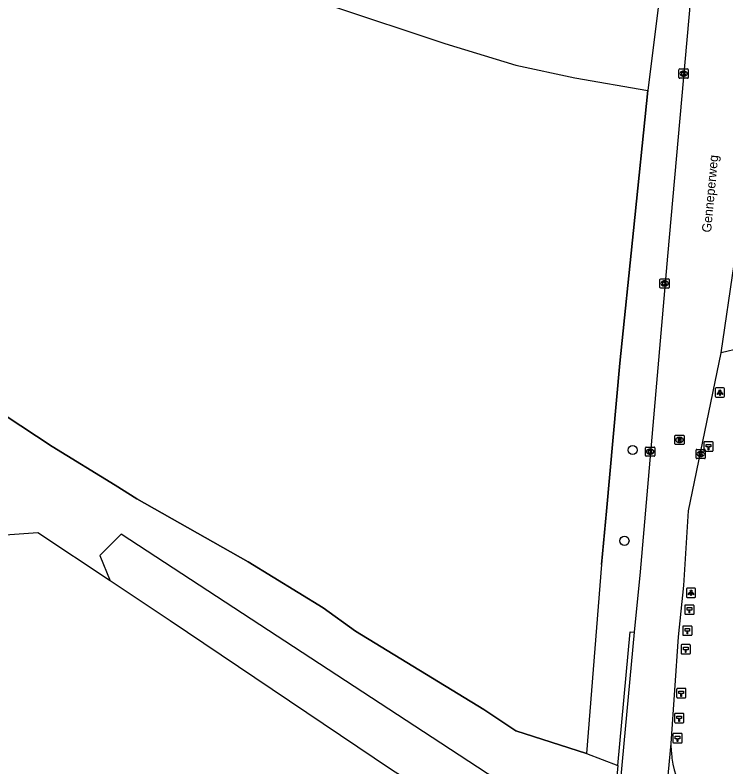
# Model space of a CAD drawing. Extents: x 160203 to 161526, y 379529 to 381797.
# Drawn here: x 160739.6 to 160816.3, y 380561.5 to 380642.7 of the extents above; entities that cross this region are included whole.
import ezdxf

# ---------------------------------------------------------------- set-up
doc = ezdxf.new("R2010")
doc.units = 0
for name, color, linetype in [('IMGEO_Boom', 7, 'Continuous'), ('IMGEO_Grasland_agrarisch', 7, 'Continuous'), ('IMGEO_Groenvoorziening', 7, 'Continuous'), ('IMGEO_Hectometerpaal', 7, 'Continuous'), ('IMGEO_Hek', 7, 'Continuous'), ('IMGEO_Kolk', 7, 'Continuous'), ('IMGEO_Lichtpunt', 7, 'Continuous'), ('IMGEO_Loofbos', 7, 'Continuous'), ('IMGEO_Openbare_ruimte_label', 7, 'Continuous'), ('IMGEO_Rijbaan_lokaal_gesloten', 7, 'Continuous'), ('IMGEO_Rijbaan_lokaal_open', 7, 'Continuous'), ('IMGEO_Rioolput', 7, 'Continuous'), ('IMGEO_Voetpad_onverhard', 7, 'Continuous')]:
    doc.layers.add(name, color=color, linetype=linetype)

msp = doc.modelspace()

# ---------------------------------------------------------------- linework, layer by layer
at = {"layer": 'IMGEO_Boom'}
for centre in [(160806.245, 380595.691), (160805.36, 380585.891)]:
    msp.add_circle(centre, 0.489, dxfattribs=at)
at = {"layer": 'IMGEO_Grasland_agrarisch'}
for points in [[(160735.875, 380657.838), (160759.659, 380648.601), (160773.611, 380643.676), (160785.98, 380639.572), (160793.624, 380637.245), (160800.015, 380635.877), (160807.89, 380634.509)], [(160807.89, 380634.509), (160806.333, 380619.409), (160804.861, 380605.066), (160803.41, 380589.083), (160802.874, 380583.321), (160801.244, 380562.921)]]:
    msp.add_lwpolyline(points, dxfattribs=at)
at = {"layer": 'IMGEO_Groenvoorziening'}
msp.add_lwpolyline([(160811.37, 380663.358), (160811.078, 380660.23), (160807.89, 380634.509)], dxfattribs=at)
at = {"layer": 'IMGEO_Hectometerpaal'}
for p, q in [((160813.932, 380596.495), (160813.932, 380595.654)), ((160813.932, 380596.495), (160813.932, 380595.654)), ((160814.848, 380596.579), (160814.007, 380596.579)), ((160814.848, 380596.579), (160814.007, 380596.579)), ((160814.932, 380595.663), (160814.932, 380596.504)), ((160814.932, 380595.663), (160814.932, 380596.504)), ((160814.016, 380595.579), (160814.857, 380595.579)), ((160814.016, 380595.579), (160814.857, 380595.579)), ((160811.87, 380578.876), (160811.87, 380578.035)), ((160811.87, 380578.876), (160811.87, 380578.035)), ((160812.786, 380578.96), (160811.945, 380578.96)), ((160812.786, 380578.96), (160811.945, 380578.96)), ((160812.87, 380578.044), (160812.87, 380578.885)), ((160812.87, 380578.044), (160812.87, 380578.885)), ((160811.954, 380577.96), (160812.795, 380577.96)), ((160811.954, 380577.96), (160812.795, 380577.96)), ((160811.65, 380576.61), (160811.65, 380575.769)), ((160811.65, 380576.61), (160811.65, 380575.769)), ((160812.566, 380576.694), (160811.725, 380576.694)), ((160812.566, 380576.694), (160811.725, 380576.694)), ((160812.65, 380575.778), (160812.65, 380576.619)), ((160812.65, 380575.778), (160812.65, 380576.619)), ((160811.734, 380575.694), (160812.575, 380575.694)), ((160811.734, 380575.694), (160812.575, 380575.694)), ((160811.475, 380574.602), (160811.475, 380573.761)), ((160811.475, 380574.602), (160811.475, 380573.761)), ((160812.391, 380574.686), (160811.55, 380574.686)), ((160812.391, 380574.686), (160811.55, 380574.686)), ((160812.475, 380573.77), (160812.475, 380574.611)), ((160812.475, 380573.77), (160812.475, 380574.611)), ((160811.559, 380573.686), (160812.4, 380573.686)), ((160811.559, 380573.686), (160812.4, 380573.686)), ((160811.909, 380569.951), (160811.068, 380569.951)), ((160811.909, 380569.951), (160811.068, 380569.951)), ((160810.993, 380569.867), (160810.993, 380569.026)), ((160810.993, 380569.867), (160810.993, 380569.026)), ((160811.993, 380569.035), (160811.993, 380569.876)), ((160811.993, 380569.035), (160811.993, 380569.876)), ((160811.077, 380568.951), (160811.918, 380568.951)), ((160811.077, 380568.951), (160811.918, 380568.951)), ((160810.763, 380567.172), (160810.763, 380566.331)), ((160810.763, 380567.172), (160810.763, 380566.331)), ((160811.679, 380567.256), (160810.838, 380567.256)), ((160811.679, 380567.256), (160810.838, 380567.256)), ((160811.763, 380566.34), (160811.763, 380567.181)), ((160811.763, 380566.34), (160811.763, 380567.181)), ((160810.847, 380566.256), (160811.688, 380566.256)), ((160810.847, 380566.256), (160811.688, 380566.256)), ((160811.503, 380565.081), (160810.662, 380565.081)), ((160811.503, 380565.081), (160810.662, 380565.081)), ((160810.587, 380564.997), (160810.587, 380564.156)), ((160810.587, 380564.997), (160810.587, 380564.156)), ((160811.587, 380564.165), (160811.587, 380565.006)), ((160811.587, 380564.165), (160811.587, 380565.006)), ((160810.671, 380564.081), (160811.512, 380564.081)), ((160810.671, 380564.081), (160811.512, 380564.081))]:
    msp.add_line(p, q, dxfattribs=at)
for points in [[(160814.457, 380595.723), (160814.397, 380595.723), (160814.397, 380596.028), (160814.177, 380596.028), (160814.177, 380596.297), (160814.677, 380596.297), (160814.677, 380596.028), (160814.457, 380596.028), (160814.457, 380595.723)], [(160812.395, 380578.104), (160812.335, 380578.104), (160812.335, 380578.409), (160812.115, 380578.409), (160812.115, 380578.678), (160812.615, 380578.678), (160812.615, 380578.409), (160812.395, 380578.409), (160812.395, 380578.104)], [(160812.175, 380575.838), (160812.115, 380575.838), (160812.115, 380576.143), (160811.895, 380576.143), (160811.895, 380576.412), (160812.395, 380576.412), (160812.395, 380576.143), (160812.175, 380576.143), (160812.175, 380575.838)], [(160812, 380573.83), (160811.94, 380573.83), (160811.94, 380574.135), (160811.72, 380574.135), (160811.72, 380574.404), (160812.22, 380574.404), (160812.22, 380574.135), (160812, 380574.135), (160812, 380573.83)], [(160811.518, 380569.095), (160811.458, 380569.095), (160811.458, 380569.4), (160811.238, 380569.4), (160811.238, 380569.669), (160811.738, 380569.669), (160811.738, 380569.4), (160811.518, 380569.4), (160811.518, 380569.095)], [(160811.288, 380566.4), (160811.228, 380566.4), (160811.228, 380566.705), (160811.008, 380566.705), (160811.008, 380566.974), (160811.508, 380566.974), (160811.508, 380566.705), (160811.288, 380566.705), (160811.288, 380566.4)], [(160811.112, 380564.225), (160811.052, 380564.225), (160811.052, 380564.53), (160810.832, 380564.53), (160810.832, 380564.799), (160811.332, 380564.799), (160811.332, 380564.53), (160811.112, 380564.53), (160811.112, 380564.225)]]:
    msp.add_lwpolyline(points, dxfattribs=at)
for centre, start, end in [((160814.01, 380596.501), 92.4484, 184.28452), ((160814.01, 380596.501), 92.4484, 184.28452), ((160814.854, 380596.501), 2.4484, 94.28452), ((160814.854, 380596.501), 2.4484, 94.28452), ((160814.01, 380595.657), 182.4484, 274.28452), ((160814.01, 380595.657), 182.4484, 274.28452), ((160814.854, 380595.657), 272.4484, 4.28452), ((160814.854, 380595.657), 272.4484, 4.28452), ((160811.948, 380578.882), 92.4484, 184.28452), ((160811.948, 380578.882), 92.4484, 184.28452), ((160812.792, 380578.882), 2.4484, 94.28452), ((160812.792, 380578.882), 2.4484, 94.28452), ((160811.948, 380578.038), 182.4484, 274.28452), ((160811.948, 380578.038), 182.4484, 274.28452), ((160812.792, 380578.038), 272.4484, 4.28452), ((160812.792, 380578.038), 272.4484, 4.28452), ((160811.728, 380576.616), 92.4484, 184.28452), ((160811.728, 380576.616), 92.4484, 184.28452), ((160812.572, 380576.616), 2.4484, 94.28452), ((160812.572, 380576.616), 2.4484, 94.28452), ((160811.728, 380575.772), 182.4484, 274.28452), ((160811.728, 380575.772), 182.4484, 274.28452), ((160812.572, 380575.772), 272.4484, 4.28452), ((160812.572, 380575.772), 272.4484, 4.28452), ((160811.553, 380574.608), 92.4484, 184.28452), ((160811.553, 380574.608), 92.4484, 184.28452), ((160812.397, 380574.608), 2.4484, 94.28452), ((160812.397, 380574.608), 2.4484, 94.28452), ((160811.553, 380573.764), 182.4484, 274.28452), ((160811.553, 380573.764), 182.4484, 274.28452), ((160812.397, 380573.764), 272.4484, 4.28452), ((160812.397, 380573.764), 272.4484, 4.28452), ((160811.071, 380569.873), 92.4484, 184.28452), ((160811.071, 380569.873), 92.4484, 184.28452), ((160811.915, 380569.873), 2.4484, 94.28452), ((160811.915, 380569.873), 2.4484, 94.28452), ((160811.071, 380569.029), 182.4484, 274.28452), ((160811.071, 380569.029), 182.4484, 274.28452), ((160811.915, 380569.029), 272.4484, 4.28452), ((160811.915, 380569.029), 272.4484, 4.28452), ((160810.841, 380567.178), 92.4484, 184.28452), ((160810.841, 380567.178), 92.4484, 184.28452), ((160811.685, 380567.178), 2.4484, 94.28452), ((160811.685, 380567.178), 2.4484, 94.28452), ((160810.841, 380566.334), 182.4484, 274.28452), ((160810.841, 380566.334), 182.4484, 274.28452), ((160811.685, 380566.334), 272.4484, 4.28452), ((160811.685, 380566.334), 272.4484, 4.28452), ((160810.665, 380565.003), 92.4484, 184.28452), ((160810.665, 380565.003), 92.4484, 184.28452), ((160811.509, 380565.003), 2.4484, 94.28452), ((160811.509, 380565.003), 2.4484, 94.28452), ((160810.665, 380564.159), 182.4484, 274.28452), ((160810.665, 380564.159), 182.4484, 274.28452), ((160811.509, 380564.159), 272.4484, 4.28452), ((160811.509, 380564.159), 272.4484, 4.28452)]:
    msp.add_arc(centre, 0.0779, start, end, dxfattribs=at)
at = {"layer": 'IMGEO_Hek'}
for points in [[(160802.874, 380583.321), (160803.41, 380589.083), (160804.861, 380605.066), (160806.333, 380619.409), (160807.89, 380634.509)], [(160721.585, 380611.503), (160724.413, 380609.361), (160726.913, 380607.468), (160734.981, 380601.724), (160743.595, 380596.079), (160750.384, 380591.884), (160752.717, 380590.443), (160764.753, 380583.637), (160772.849, 380578.66), (160776.314, 380576.149), (160790.192, 380567.674), (160793.641, 380565.361), (160801.244, 380562.921)]]:
    msp.add_lwpolyline(points, dxfattribs=at)
at = {"layer": 'IMGEO_Kolk'}
for p, q in [((160811.242, 380635.908), (160811.242, 380636.76)), ((160811.317, 380636.834), (160812.169, 380636.834)), ((160811.73, 380636.614), (160811.755, 380636.614)), ((160812.243, 380636.76), (160812.243, 380635.908)), ((160812.169, 380635.834), (160811.317, 380635.834)), ((160811.753, 380636.054), (160811.728, 380636.054)), ((160809.191, 380613.254), (160809.191, 380614.106)), ((160809.266, 380614.18), (160810.118, 380614.18)), ((160809.679, 380613.96), (160809.704, 380613.96)), ((160810.192, 380614.106), (160810.192, 380613.254)), ((160810.118, 380613.18), (160809.266, 380613.18)), ((160809.702, 380613.4), (160809.677, 380613.4)), ((160807.635, 380595.094), (160807.635, 380595.946)), ((160807.71, 380596.02), (160808.562, 380596.02)), ((160808.636, 380595.946), (160808.636, 380595.094)), ((160808.146, 380595.24), (160808.121, 380595.24)), ((160808.123, 380595.8), (160808.148, 380595.8)), ((160813.084, 380594.84), (160813.084, 380595.692)), ((160813.159, 380595.766), (160814.011, 380595.766)), ((160813.572, 380595.546), (160813.597, 380595.546)), ((160814.085, 380595.692), (160814.085, 380594.84)), ((160808.562, 380595.02), (160807.71, 380595.02)), ((160814.011, 380594.766), (160813.159, 380594.766)), ((160813.595, 380594.986), (160813.57, 380594.986))]:
    msp.add_line(p, q, dxfattribs=at)
for points in [[(160811.242, 380635.908), (160811.242, 380636.76)], [(160811.317, 380636.834), (160812.169, 380636.834)], [(160811.563, 380636.534), (160811.686, 380636.534), (160811.686, 380636.383), (160811.816, 380636.534), (160811.98, 380636.534), (160811.834, 380636.383), (160811.987, 380636.134), (160811.835, 380636.134), (160811.75, 380636.298), (160811.686, 380636.231), (160811.686, 380636.134), (160811.563, 380636.134), (160811.563, 380636.534)], [(160812.243, 380636.76), (160812.243, 380635.908)], [(160812.169, 380635.834), (160811.317, 380635.834)], [(160809.191, 380613.254), (160809.191, 380614.106)], [(160809.266, 380614.18), (160810.118, 380614.18)], [(160809.512, 380613.88), (160809.635, 380613.88), (160809.635, 380613.729), (160809.765, 380613.88), (160809.929, 380613.88), (160809.783, 380613.729), (160809.936, 380613.48), (160809.784, 380613.48), (160809.699, 380613.644), (160809.635, 380613.577), (160809.635, 380613.48), (160809.512, 380613.48), (160809.512, 380613.88)], [(160810.192, 380614.106), (160810.192, 380613.254)], [(160810.118, 380613.18), (160809.266, 380613.18)], [(160807.635, 380595.094), (160807.635, 380595.946)], [(160807.71, 380596.02), (160808.562, 380596.02)], [(160808.636, 380595.946), (160808.636, 380595.094)], [(160807.956, 380595.72), (160808.079, 380595.72), (160808.079, 380595.569), (160808.209, 380595.72), (160808.373, 380595.72), (160808.227, 380595.569), (160808.38, 380595.32), (160808.228, 380595.32), (160808.143, 380595.484), (160808.079, 380595.417), (160808.079, 380595.32), (160807.956, 380595.32), (160807.956, 380595.72)], [(160813.084, 380594.84), (160813.084, 380595.692)], [(160813.159, 380595.766), (160814.011, 380595.766)], [(160813.405, 380595.466), (160813.528, 380595.466), (160813.528, 380595.315), (160813.658, 380595.466), (160813.822, 380595.466), (160813.676, 380595.315), (160813.829, 380595.066), (160813.677, 380595.066), (160813.592, 380595.23), (160813.528, 380595.163), (160813.528, 380595.066), (160813.405, 380595.066), (160813.405, 380595.466)], [(160814.085, 380595.692), (160814.085, 380594.84)], [(160808.562, 380595.02), (160807.71, 380595.02)], [(160814.011, 380594.766), (160813.159, 380594.766)]]:
    msp.add_lwpolyline(points, dxfattribs=at)
for centre, start, end in [((160811.319, 380636.758), 91.55205, 178.44795), ((160811.319, 380636.758), 91.55205, 178.44795), ((160812.167, 380636.758), 1.55205, 88.44795), ((160812.167, 380636.758), 1.55205, 88.44795), ((160811.319, 380635.91), 181.55205, 268.44795), ((160811.319, 380635.91), 181.55205, 268.44795), ((160812.167, 380635.91), 271.55205, 358.44795), ((160812.167, 380635.91), 271.55205, 358.44795), ((160809.268, 380614.104), 91.55205, 178.44795), ((160809.268, 380614.104), 91.55205, 178.44795), ((160810.116, 380614.104), 1.55205, 88.44795), ((160810.116, 380614.104), 1.55205, 88.44795), ((160809.268, 380613.256), 181.55205, 268.44795), ((160809.268, 380613.256), 181.55205, 268.44795), ((160810.116, 380613.256), 271.55205, 358.44795), ((160810.116, 380613.256), 271.55205, 358.44795), ((160807.712, 380595.944), 91.55205, 178.44795), ((160807.712, 380595.944), 91.55205, 178.44795), ((160808.56, 380595.944), 1.55205, 88.44795), ((160808.56, 380595.944), 1.55205, 88.44795), ((160813.161, 380595.69), 91.55205, 178.44795), ((160813.161, 380595.69), 91.55205, 178.44795), ((160814.009, 380595.69), 1.55205, 88.44795), ((160814.009, 380595.69), 1.55205, 88.44795), ((160807.712, 380595.096), 181.55205, 268.44795), ((160807.712, 380595.096), 181.55205, 268.44795), ((160808.56, 380595.096), 271.55205, 358.44795), ((160808.56, 380595.096), 271.55205, 358.44795), ((160813.161, 380594.842), 181.55205, 268.44795), ((160813.161, 380594.842), 181.55205, 268.44795), ((160814.009, 380594.842), 271.55205, 358.44795), ((160814.009, 380594.842), 271.55205, 358.44795)]:
    msp.add_arc(centre, 0.0765, start, end, dxfattribs=at)
for centre, major_axis, ratio, start_param, end_param in [((160811.729, 380636.334), (-0.387, 0.002), 0.722429, 4.712389, 7.853982), ((160811.754, 380636.334), (-0.39, 0.002), 0.717154, 1.570796, 4.712389), ((160809.678, 380613.68), (-0.387, 0.002), 0.722429, 4.712389, 7.853982), ((160809.703, 380613.68), (-0.39, 0.002), 0.717154, 1.570796, 4.712389), ((160808.122, 380595.52), (-0.387, 0.002), 0.722429, 4.712389, 7.853982), ((160808.147, 380595.52), (-0.39, 0.002), 0.717154, 1.570796, 4.712389), ((160813.571, 380595.266), (-0.387, 0.002), 0.722429, 4.712389, 7.853982), ((160813.596, 380595.266), (-0.39, 0.002), 0.717154, 1.570796, 4.712389)]:
    msp.add_ellipse(centre, major_axis=major_axis, ratio=ratio, start_param=start_param, end_param=end_param, dxfattribs=at)
at = {"layer": 'IMGEO_Lichtpunt'}
for p, q in [((160815.164, 380602.302), (160815.164, 380601.495)), ((160815.164, 380602.302), (160815.164, 380601.495)), ((160816.066, 380602.397), (160815.258, 380602.397)), ((160816.066, 380602.397), (160815.258, 380602.397)), ((160816.16, 380601.495), (160816.16, 380602.302)), ((160816.16, 380601.495), (160816.16, 380602.302)), ((160815.258, 380601.401), (160816.066, 380601.401)), ((160815.258, 380601.401), (160816.066, 380601.401)), ((160812.045, 380580.684), (160812.045, 380579.877)), ((160812.045, 380580.684), (160812.045, 380579.877)), ((160812.947, 380580.779), (160812.139, 380580.779)), ((160812.947, 380580.779), (160812.139, 380580.779)), ((160813.041, 380579.877), (160813.041, 380580.684)), ((160813.041, 380579.877), (160813.041, 380580.684)), ((160812.139, 380579.783), (160812.947, 380579.783)), ((160812.139, 380579.783), (160812.947, 380579.783))]:
    msp.add_line(p, q, dxfattribs=at)
for points in [[(160815.538, 380601.966), (160815.577, 380601.938), (160815.389, 380601.676), (160815.351, 380601.703), (160815.538, 380601.966)], [(160815.64, 380601.918), (160815.687, 380601.918), (160815.687, 380601.596), (160815.64, 380601.596), (160815.64, 380601.918)], [(160815.75, 380601.938), (160815.788, 380601.965), (160815.975, 380601.703), (160815.936, 380601.675), (160815.75, 380601.938)], [(160812.419, 380580.348), (160812.458, 380580.32), (160812.27, 380580.058), (160812.232, 380580.085), (160812.419, 380580.348)], [(160812.521, 380580.3), (160812.568, 380580.3), (160812.568, 380579.978), (160812.521, 380579.978), (160812.521, 380580.3)], [(160812.631, 380580.32), (160812.669, 380580.347), (160812.856, 380580.085), (160812.817, 380580.057), (160812.631, 380580.32)]]:
    msp.add_lwpolyline(points, dxfattribs=at)
for centre in [(160815.663, 380602.1), (160812.544, 380580.482)]:
    msp.add_circle(centre, 0.0994, dxfattribs=at)
for centre, start, end in [((160815.258, 380602.302), 90, 180), ((160815.258, 380602.302), 90, 180), ((160816.066, 380602.302), 0, 90), ((160816.066, 380602.302), 0, 90), ((160815.258, 380601.495), 180, 270), ((160815.258, 380601.495), 180, 270), ((160816.066, 380601.495), 270, 0), ((160816.066, 380601.495), 270, 360), ((160812.139, 380580.684), 90, 180), ((160812.139, 380580.684), 90, 180), ((160812.947, 380580.684), 0, 90), ((160812.947, 380580.684), 0, 90), ((160812.139, 380579.877), 180, 270), ((160812.139, 380579.877), 180, 270), ((160812.947, 380579.877), 270, 0), ((160812.947, 380579.877), 270, 360)]:
    msp.add_arc(centre, 0.0946, start, end, dxfattribs=at)
at = {"layer": 'IMGEO_Loofbos'}
msp.add_lwpolyline([(160717.981, 380545.126), (160744.656, 380526.724), (160784.788, 380499.117), (160785.05, 380500.373), (160788.367, 380529.846), (160786.228, 380546.866), (160784.742, 380557.013), (160783.061, 380559.385), (160780.198, 380561.178), (160756.304, 380577.252), (160749.852, 380581.558)], dxfattribs=at)
at = {"layer": 'IMGEO_Rijbaan_lokaal_gesloten'}
for points in [[(160814.161, 380663.374), (160809.998, 380616.634), (160807.06, 380582.557), (160806.416, 380576.035)], [(160815.809, 380606.179), (160817.202, 380615.762)], [(160810.392, 380564.026), (160811.178, 380575.524), (160811.772, 380581.086), (160812.279, 380589.127), (160815.809, 380606.179)], [(160806.416, 380576.035), (160803.96, 380549.663)], [(160809.041, 380549.44), (160810.392, 380564.026)], [(160810.426, 380563.07), (160810.392, 380564.026)]]:
    msp.add_lwpolyline(points, dxfattribs=at)
msp.add_arc((160818.108, 380563.255), 7.684, 181.38232, 256.20947, dxfattribs=at)
at = {"layer": 'IMGEO_Rijbaan_lokaal_open'}
for points in [[(160817.907, 380606.678), (160815.809, 380606.179)], [(160804.651, 380561.649), (160805.988, 380576.064), (160806.416, 380576.035)], [(160804.651, 380561.649), (160804.321, 380558.092)]]:
    msp.add_lwpolyline(points, dxfattribs=at)
at = {"layer": 'IMGEO_Rioolput'}
for p, q in [((160810.8, 380596.364), (160810.8, 380597.216)), ((160810.875, 380597.29), (160811.727, 380597.29)), ((160811.288, 380597.07), (160811.313, 380597.07)), ((160811.801, 380597.216), (160811.801, 380596.364)), ((160811.727, 380596.29), (160810.875, 380596.29)), ((160811.311, 380596.51), (160811.286, 380596.51))]:
    msp.add_line(p, q, dxfattribs=at)
for points in [[(160810.8, 380596.364), (160810.8, 380597.216)], [(160810.875, 380597.29), (160811.727, 380597.29)], [(160811.389, 380596.988), (160811.137, 380596.99), (160811.137, 380596.59)], [(160811.137, 380596.59), (160811.261, 380596.59), (160811.261, 380596.752), (160811.272, 380596.752)], [(160811.315, 380596.909), (160811.261, 380596.909), (160811.261, 380596.828)], [(160811.261, 380596.828), (160811.313, 380596.828)], [(160811.801, 380597.216), (160811.801, 380596.364)], [(160811.727, 380596.29), (160810.875, 380596.29)], [(160811.319, 380596.723), (160811.39, 380596.59), (160811.53, 380596.59), (160811.465, 380596.716)]]:
    msp.add_lwpolyline(points, dxfattribs=at)
for centre, radius, start, end in [((160810.877, 380597.214), 0.0765, 91.55205, 178.44795), ((160810.877, 380597.214), 0.0765, 91.55205, 178.44795), ((160811.271, 380596.699), 0.0533, 26.02933, 88.69889), ((160811.297, 380597.017), 0.19, 274.7715, 282.96867), ((160811.321, 380596.813), 0.0964, 77.00612, 93.18647), ((160811.335, 380596.87), 0.0378, 276.66336, 79.67722), ((160811.388, 380596.878), 0.109, 350.36119, 89.41601), ((160811.386, 380596.878), 0.112, 277.58423, 350.98172), ((160811.37, 380596.663), 0.108, 29.51342, 73.79051), ((160811.725, 380597.214), 0.0765, 1.55205, 88.44795), ((160811.725, 380597.214), 0.0765, 1.55205, 88.44795), ((160810.877, 380596.366), 0.0765, 181.55205, 268.44795), ((160810.877, 380596.366), 0.0765, 181.55205, 268.44795), ((160811.725, 380596.366), 0.0765, 271.55205, 358.44795), ((160811.725, 380596.366), 0.0765, 271.55205, 358.44795)]:
    msp.add_arc(centre, radius, start, end, dxfattribs=at)
for centre, major_axis, ratio, start_param, end_param in [((160811.287, 380596.79), (-0.387, 0.002), 0.722429, 4.712389, 7.853982), ((160811.312, 380596.79), (-0.39, 0.002), 0.717154, 1.570796, 4.712389)]:
    msp.add_ellipse(centre, major_axis=major_axis, ratio=ratio, start_param=start_param, end_param=end_param, dxfattribs=at)
at = {"layer": 'IMGEO_Voetpad_onverhard'}
for points in [[(160801.244, 380562.921), (160793.641, 380565.361), (160790.192, 380567.674), (160776.314, 380576.149), (160772.849, 380578.66), (160764.753, 380583.637), (160752.717, 380590.443), (160750.384, 380591.884), (160743.595, 380596.079), (160734.981, 380601.724), (160726.913, 380607.468), (160724.413, 380609.361)], [(160749.852, 380581.558), (160742.051, 380586.766), (160738.012, 380586.465)], [(160792.511, 380559.49), (160785.554, 380564.034), (160751.047, 380586.623), (160748.717, 380584.317), (160749.852, 380581.558)], [(160801.244, 380562.921), (160804.651, 380561.649)]]:
    msp.add_lwpolyline(points, dxfattribs=at)

# ---------------------------------------------------------------- texts
at = {"layer": 'IMGEO_Openbare_ruimte_label'}
msp.add_text('Genneperweg', height=1, rotation=84.66556, dxfattribs=at).set_placement((160814.701, 380619.145))

doc.saveas('drawing.dxf')
